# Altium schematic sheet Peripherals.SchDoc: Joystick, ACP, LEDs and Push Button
size A4; Date: 01-DEC-2013; Author: A.B; CompanyName: STMicroelectronics; Organization: Microcontrollers Division; Address1: 12, Rue Jules HOROWITZ; Address2: 38019 Grenoble; Address3: FRANCE; DocumentNumber: MB1184; Revision: C-01; SheetNumber: 5; SheetTotal: 10; Project: STM32L476G-DISCO
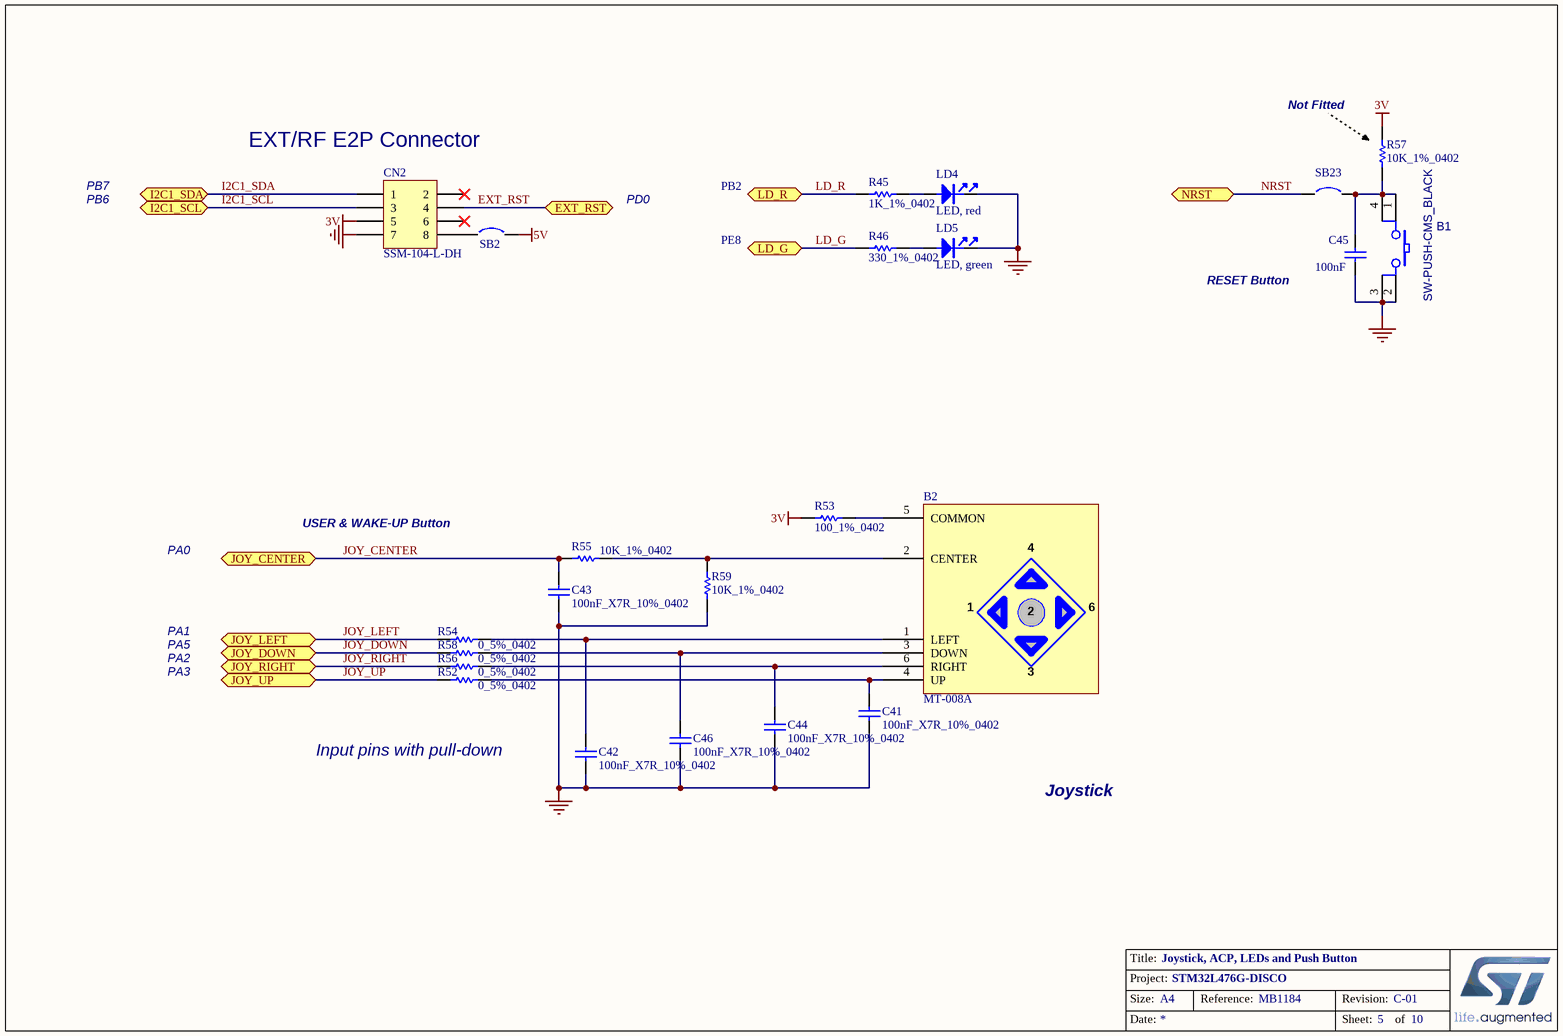
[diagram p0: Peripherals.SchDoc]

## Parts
B1  SW-PUSH-CMS_BLACK  [BP1CMS]
B2  MT-008A  [MT-008A]
C41  100nF_X7R_10%_0402  [0402C]
C42  100nF_X7R_10%_0402  [0402C]
C43  100nF_X7R_10%_0402  [0402C]
C44  100nF_X7R_10%_0402  [0402C]
C45  100nF  [0402C]
C46  100nF_X7R_10%_0402  [0402C]
CN2  SSM-104-L-DH  [SSM-104-L-DH]
LD4  LED, red  [0603D]
LD5  LED, green  [0603D]
R45  1K_1%_0402  [0402R]
R46  330_1%_0402  [0402R]
R52  0_5%_0402  [0402R]
R53  100_1%_0402  [0402R]
R54  0_5%_0402  [0402R]
R55  10K_1%_0402  [0402R]
R56  0_5%_0402  [0402R]
R57  10K_1%_0402  [0402R]
R58  0_5%_0402  [0402R]
R59  10K_1%_0402  [0402R]
SB2  Circuit Breaker  [JP2_SMD]  (value not drawn)
SB23  Circuit Breaker  [JP2_SMD]  (value not drawn)

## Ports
EXT_RST, I2C1_SCL, I2C1_SDA, JOY_CENTER, JOY_DOWN, JOY_LEFT, JOY_RIGHT, JOY_UP, LD_G, LD_R, NRST

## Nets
3V: CN2.5 R53.1 R57.2
5V: SB2.2
GND: B1.2 B1.3 C41.1 C42.1 C43.1 C44.1 C45.1 C46.1 CN2.7 LD4.2 LD5.2 R59.1
EXT_RST: CN2.4 ; port EXT_RST
I2C1_SCL: CN2.3 ; port I2C1_SCL
I2C1_SDA: CN2.1 ; port I2C1_SDA
JOY_CENTER: C43.2 R55.1 ; port JOY_CENTER
JOY_DOWN: R58.1 ; port JOY_DOWN
JOY_LEFT: R54.1 ; port JOY_LEFT
JOY_RIGHT: R56.1 ; port JOY_RIGHT
JOY_UP: R52.1 ; port JOY_UP
LD_G: R46.1 ; port LD_G
LD_R: R45.1 ; port LD_R
NRST: SB23.1 ; port NRST
NetB1_1: B1.1 B1.4 C45.2 R57.1 SB23.2
NetB2_1: B2.1(LEFT) C42.2 R54.2
NetB2_2: B2.2(CENTER) R55.2 R59.2
NetB2_3: B2.3(DOWN) C46.2 R58.2
NetB2_4: B2.4(UP) C41.2 R52.2
NetB2_5: B2.5(COMMON) R53.2
NetB2_6: B2.6(RIGHT) C44.2 R56.2
NetCN2_8: CN2.8 SB2.1
NetLD4_1: LD4.1 R45.2
NetLD5_1: LD5.1 R46.2

Not connected (* = marked no-connect by the designer): CN2 2* 6*

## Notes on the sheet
- (near R57) Not Fitted
- (near CN2) EXT/RF E2P Connector
- PB6
- PB7
- PD0
- PB2
- PE8
- RESET Button
- PA0
- USER & WAKE-UP Button
- PA1
- PA5
- PA2
- PA3
- Input pins with pull-down
- Joystick

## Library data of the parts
B1 = SW-PUSH-CMS_BLACK: Non-Open Push-Button 0.1A 24V; Manuf_2: FARNELL; Manuf_Part_2: 535-930; Manuf_1: wealthmetal; Manuf_Part_1: TD0341X-G01-BLA; Ref St: 9180120; Description: Non-Open Push Button,Black 0.1A 24V,Square head,6*6,SMT,180Degree,TD-0341X-GO1,wealthmetal
B2 = MT-008A: Joystick with Hat, Multi Function Switch; Manuf_1: XIEJIA Electronics
C41-C46 = Cap_100nF_X7R_10%_0402: Capacitor,100nF,16V,X7R,10%,0402,YAGEO; Manuf_Part_1: CC0402KRX7R7BB104
CN2 = SSM-104-L-DH: Header, 5-Pin, Dual row
LD4 = LED_red: LED, red, 0603; Manuf_1: everlight; Manuf_Part_1: 19-213-R6C-AP1Q2B/3T; Description: LED,red,0603,19-213-R6C-AP1Q2B/3T,everlight; ECCN_US/EU: EAR99/NEC
LD5 = LED_green: LED, green, 0603; Manuf_1: everlight; Manuf_Part_1: 19-213SYGC/S530-E2/TR8; Description: LED,green,0603,19-213SYGC/S530-E2/TR8,everlight; ECCN_US/EU: EAR99/NEC
R45 = Res_1K_1%_0402: Resistor,1K,0402,1%,YAGEO; Manuf_Part_1: RC0402FR-071KL
R46 = Res_330_1%_0402: Resistor,330,0402,1%,YAGEO; Manuf_Part_1: RC0402FR-07330RL; Value: 330
R52 R54 R56 R58 = Res_0_5%_0402: Resistor,0,0402,5%,YAGEO; Manuf_Part_1: RC0402JR-070RL; Value: 0; Order: 2363467
R53 = Res_100_1%_0402: Resistor,100,0402,1%,YAGEO; Manuf_Part_1: RC0402FR-07100RL; Value: 100; Order: 9239111
R55 R59 = Res_10K_1%_0402: Resistor,10K,0402,1%,YAGEO; Manuf_Part_1: RC0402FR-0710KL
R57 = Res_10K_1%_0402: Resistor,10K,0402,1%,YAGEO; Manuf_Part_1: RC0402FR-0710KL; Fitted: NO
SB2 = Circuit Breaker: Solder: NO
SB23 = Circuit Breaker: Solder: YES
